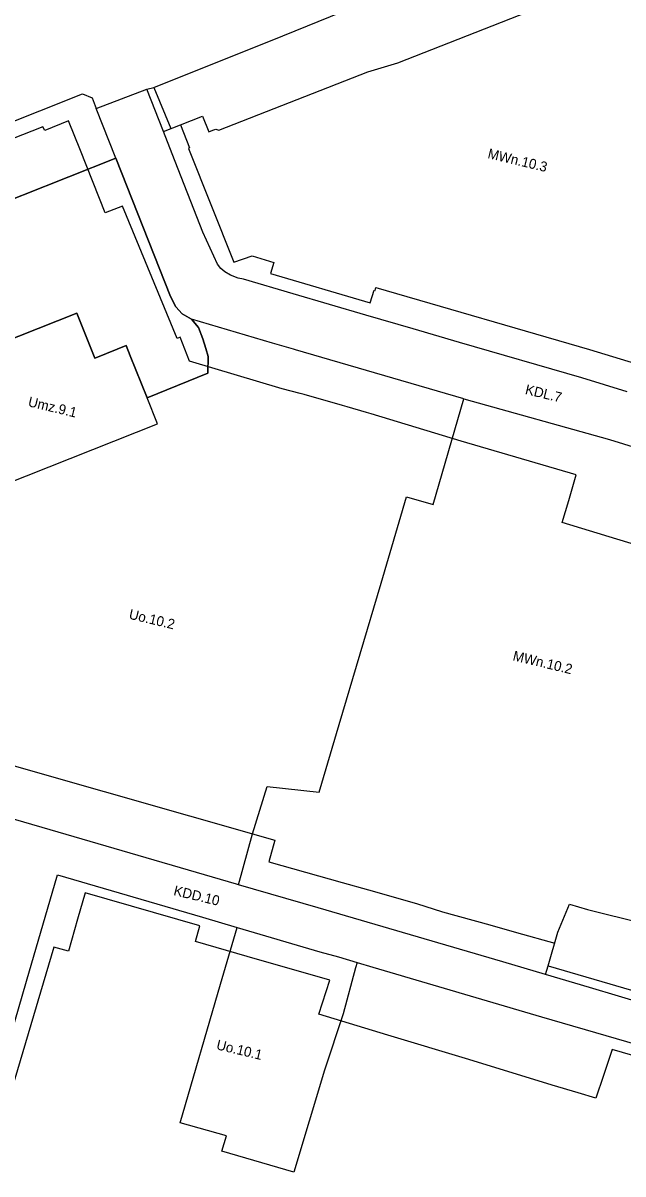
# Model space of a CAD drawing. Extents: x 7429686 to 7432896, y 5547954 to 5550600.
# Drawn here: x 7431748.3 to 7431989.8, y 5548706.1 to 5549169.6 of the extents above; entities that cross this region are included whole.
import ezdxf

# ---------------------------------------------------------------- set-up
doc = ezdxf.new("R2010")
doc.units = 0
for name, color, linetype in [('linie rozgraniczające', 7, 'Continuous'), ('obowiązująca linia zabudowy', 7, 'Continuous'), ('oznaczenia przeznaczeń', 7, 'Continuous')]:
    doc.layers.add(name, color=color, linetype=linetype)

msp = doc.modelspace()

# ---------------------------------------------------------------- linework, layer by layer
at = {"layer": 'linie rozgraniczające'}
for p, q in [((7431785.66, 5549115.2), (7431504.99, 5549003.74)), ((7431818.9, 5549046.91), (7431816.06, 5549050.34)), ((7431820.72, 5549042.45), (7431818.9, 5549046.91))]:
    msp.add_line(p, q, dxfattribs=at)
for points in [[(7431899.21, 5549153.61), (7431965.2, 5549179.6)], [(7431852.81, 5549164.49), (7431877.01, 5549174.22)], [(7431800.96, 5549143.64), (7431852.81, 5549164.49)], [(7431887.04, 5549149.97), (7431899.21, 5549153.61)], [(7431827.07, 5549126.43), (7431887.04, 5549149.97)], [(7431798.07, 5549142.96), (7431800.96, 5549143.64)], [(7431684.85, 5549106.33), (7431772.2, 5549141.08)], [(7431772.2, 5549141.08), (7431776.09, 5549139.4)], [(7431776.09, 5549139.4), (7431777.75, 5549135.22)], [(7431777.75, 5549135.22), (7431798.07, 5549142.96)], [(7431804.77, 5549125.9), (7431798.07, 5549142.96)], [(7431785.66, 5549115.2), (7431777.75, 5549135.22)], [(7431811.66, 5549128.55), (7431820.52, 5549132.11)], [(7431820.52, 5549132.11), (7431823.02, 5549125.78)], [(7431804.77, 5549125.9), (7431811.66, 5549128.55)], [(7431808.3, 5549116.89), (7431804.77, 5549125.9)], [(7431823.02, 5549125.78), (7431824.7, 5549126.43)], [(7431824.7, 5549126.43), (7431825.89, 5549126.82)], [(7431825.89, 5549126.82), (7431827.07, 5549126.43)], [(7431820.72, 5549085.42), (7431808.3, 5549116.89)], [(7431487.65, 5549002.56), (7431490.16, 5549003.53), (7431491.56, 5549004.06), (7431499.75, 5549007.52), (7431502.92, 5549008.85), (7431504.99, 5549003.74), (7431785.66, 5549115.2)], [(7431816.06, 5549050.34), (7431812.4, 5549052.53), (7431809.72, 5549055.33), (7431807.68, 5549059.45), (7431785.66, 5549115.2)], [(7431785.66, 5549115.2), (7431807.68, 5549059.45)], [(7431826.53, 5549072.49), (7431820.72, 5549085.42)], [(7431827.87, 5549070.74), (7431826.53, 5549072.49)], [(7431829.46, 5549069.35), (7431827.87, 5549070.74)], [(7431831.77, 5549067.99), (7431829.46, 5549069.35)], [(7431834.88, 5549066.87), (7431831.77, 5549067.99)], [(7431837.02, 5549066.39), (7431834.88, 5549066.87)], [(7431857.03, 5549060.51), (7431837.02, 5549066.39)], [(7431886.31, 5549051.9), (7431857.03, 5549060.51)], [(7431807.68, 5549059.45), (7431809.72, 5549055.33), (7431812.4, 5549052.53), (7431816.06, 5549050.34)], [(7431798.27, 5549018.65), (7431791.38, 5549035.58), (7431789.74, 5549039.66), (7431778.26, 5549035.05), (7431777.18, 5549034.62), (7431769.87, 5549052.73), (7431730.81, 5549037.32), (7431734.44, 5549028.21), (7431724.7, 5549024.21), (7431741.14, 5548983.95)], [(7431734.44, 5549028.21), (7431730.81, 5549037.32), (7431769.87, 5549052.73), (7431777.18, 5549034.62), (7431778.26, 5549035.05)], [(7431905.33, 5549046.39), (7431886.31, 5549051.9)], [(7431816.06, 5549050.34), (7431818.9, 5549046.91), (7431820.72, 5549042.45), (7431821.8, 5549038.55), (7431822.85, 5549035.29), (7431822.73, 5549028.6), (7431798.27, 5549018.65)], [(7431848.77, 5549040.69), (7431816.06, 5549050.34)], [(7431923.98, 5549040.97), (7431905.33, 5549046.39)], [(7431798.27, 5549018.65), (7431822.73, 5549028.6), (7431822.85, 5549035.29), (7431821.8, 5549038.55), (7431820.72, 5549042.45)], [(7431778.26, 5549035.05), (7431789.74, 5549039.66), (7431791.38, 5549035.58), (7431798.27, 5549018.65)], [(7431857.11, 5549038.25), (7431848.77, 5549040.69)], [(7431857.94, 5549038.01), (7431857.11, 5549038.25)], [(7431925.7, 5549018.22), (7431857.94, 5549038.01)], [(7431973.2, 5549026.64), (7431923.98, 5549040.97)], [(7431991.53, 5549021.11), (7431973.2, 5549026.64)], [(7431802.38, 5549008.24), (7431798.27, 5549018.65)], [(7431913.39, 5548975.67), (7431925.7, 5549018.22)], [(7431925.7, 5549018.22), (7431984.36, 5549001.84)], [(7431741.14, 5548983.95), (7431802.38, 5549008.24)], [(7431984.36, 5549001.84), (7432016.11, 5548992.11)], [(7431892.44, 5548944.03), (7431902.71, 5548978.75)], [(7431902.71, 5548978.75), (7431913.39, 5548975.67)], [(7431875.57, 5548887.09), (7431892.44, 5548944.03)], [(7431867.53, 5548859.9), (7431875.57, 5548887.09)], [(7431840.64, 5548843.13), (7431846.53, 5548862.17)], [(7431846.53, 5548862.17), (7431867.53, 5548859.9)], [(7431834.22, 5548822.81), (7431725.87, 5548854.38)], [(7431834.99, 5548822.59), (7431840.64, 5548843.13)], [(7431749.67, 5548783.7), (7431762.16, 5548826.62)], [(7431762.16, 5548826.62), (7431820.54, 5548809.52)], [(7431834.99, 5548822.59), (7431834.22, 5548822.81)], [(7431867.06, 5548813.22), (7431834.99, 5548822.59)], [(7431963.65, 5548803.42), (7431968.28, 5548814.7)], [(7431968.28, 5548814.7), (7431975.55, 5548812.55)], [(7431941.41, 5548791.48), (7431867.06, 5548813.22)], [(7431975.55, 5548812.55), (7431997.73, 5548807.08)], [(7431820.54, 5548809.52), (7431834.42, 5548805.4)], [(7431827.76, 5548782.57), (7431834.42, 5548805.4)], [(7431834.42, 5548805.4), (7431867.77, 5548795.62)], [(7431959.7, 5548789.91), (7431963.65, 5548803.42)], [(7431867.77, 5548795.62), (7431875.31, 5548793.5)], [(7431875.31, 5548793.5), (7431882.8, 5548791.22)], [(7431958.67, 5548786.41), (7431941.41, 5548791.48)], [(7431882.16, 5548789.08), (7431877.13, 5548770.53)], [(7431882.8, 5548791.22), (7431882.16, 5548789.08)], [(7431882.8, 5548791.22), (7431889.09, 5548789.36)], [(7431889.09, 5548789.36), (7431956.98, 5548769.32)], [(7431958.67, 5548786.41), (7431959.7, 5548789.91)], [(7431731.33, 5548720.67), (7431749.67, 5548783.7)], [(7431811.48, 5548726.7), (7431827.76, 5548782.57)], [(7431976.39, 5548781.2), (7431958.67, 5548786.41)], [(7431999.67, 5548774.22), (7431976.39, 5548781.2)], [(7431877.13, 5548770.53), (7431869.71, 5548747.96)], [(7431956.98, 5548769.32), (7432038.88, 5548745.56)], [(7431869.71, 5548747.96), (7431857.26, 5548706.84)], [(7431830.18, 5548721.4), (7431811.48, 5548726.7)], [(7431828.36, 5548715.23), (7431830.18, 5548721.4)], [(7431857.26, 5548706.84), (7431828.36, 5548715.23)]]:
    msp.add_lwpolyline(points, dxfattribs=at)
at = {"layer": 'obowiązująca linia zabudowy'}
msp.add_line((7431800.96, 5549143.64), (7431807.79, 5549127.06), dxfattribs=at)
for points in [[(7431766.61, 5549130.17), (7431756.99, 5549126.27), (7431756.29, 5549127.83), (7431735.31, 5549119.54)], [(7431815.25, 5549033.35), (7431811.58, 5549043.03), (7431810.34, 5549042.58), (7431788.37, 5549095.82), (7431781.4, 5549093.12), (7431771.39, 5549118.2), (7431766.61, 5549130.17)], [(7431811.66, 5549128.55), (7431815.33, 5549119.34), (7431814.86, 5549119.06), (7431833.18, 5549073.22), (7431840.48, 5549075.78), (7431849.25, 5549073.09), (7431847.84, 5549068.66), (7431888.06, 5549056.88), (7431889.59, 5549061.99), (7431890.02, 5549061.88), (7431890.36, 5549063.02)], [(7431890.36, 5549063.02), (7431976.32, 5549038.08), (7431994.91, 5549032.49), (7432055.44, 5549014.62), (7432056.03, 5549016.4), (7432065.38, 5549013.54), (7432064.81, 5549011.51), (7432078.91, 5549007.17), (7432082.2, 5549019.17), (7432105.85, 5549011.75), (7432117.86, 5549008.18), (7432204.39, 5548982.49), (7432203.42, 5548979.11), (7432202.88, 5548979.27), (7432201.05, 5548972.89), (7432216.61, 5548968.41), (7432221.56, 5548985.6), (7432224.91, 5548984.63), (7432230.18, 5549002.93), (7432227.09, 5549003.82), (7432232.12, 5549021.29), (7432233.49, 5549026.51), (7432234.43, 5549030.05)], [(7431924.63, 5549001.26), (7431888.4, 5549012.24), (7431886.6, 5549012.76), (7431878.76, 5549015.01), (7431876.93, 5549015.56), (7431861.48, 5549019.93), (7431859.81, 5549020.41), (7431852.65, 5549022.34), (7431815.25, 5549033.35)], [(7432073.79, 5548794.14), (7432077.22, 5548807.01), (7432082.7, 5548826), (7432091.23, 5548855.14), (7432084.49, 5548857.14), (7432087.31, 5548866.67), (7432095.91, 5548895.72), (7432088.95, 5548897.74), (7432091.76, 5548907.42), (7432100.2, 5548936.45), (7432091.13, 5548939.15), (7432097.14, 5548960.46), (7432050.78, 5548973.93), (7432048.2, 5548965.02), (7432043.53, 5548948.94), (7432034.3, 5548951.81), (7432033.11, 5548947.97), (7431987.31, 5548961.78), (7431965.36, 5548968.4), (7431967.98, 5548977.35), (7431971, 5548987.66), (7431924.63, 5549001.26)], [(7431577.21, 5548911.2), (7431589.18, 5548907.8), (7431611.32, 5548901.4), (7431623.3, 5548897.83), (7431645.57, 5548891.16), (7431657.48, 5548887.86), (7431679.82, 5548881.19), (7431691.72, 5548877.82), (7431693.9, 5548885.03), (7431746.6, 5548869.97), (7431849.61, 5548840.54), (7431847.29, 5548831.84)], [(7431847.29, 5548831.84), (7431876.82, 5548823.45), (7431887.41, 5548820.48), (7431906.7, 5548814.98), (7431917.22, 5548811.73), (7431936.27, 5548806.45), (7431947, 5548803.38), (7431962.35, 5548798.99)], [(7431773.26, 5548819.35), (7431770.21, 5548808.72), (7431766.52, 5548795.89), (7431760.63, 5548797.5), (7431747.1, 5548751.63), (7431737.24, 5548718.65), (7431724.14, 5548672.46)], [(7432031.3, 5548742.89), (7431985.51, 5548756.24), (7431981.99, 5548745.69), (7431978.94, 5548736.59), (7431971.72, 5548738.72), (7431961.26, 5548741.82), (7431927.75, 5548752.14), (7431895.14, 5548762.01), (7431867.41, 5548770.39), (7431871.83, 5548784.12), (7431838.53, 5548793.74), (7431817.65, 5548799.78), (7431819.43, 5548806.02), (7431773.26, 5548819.35)], [(7431959.7, 5548789.91), (7431993.26, 5548780.1), (7432004.46, 5548776.66), (7432016.7, 5548773.07), (7432020.19, 5548784.68), (7432022.6, 5548784), (7432022.51, 5548783.46), (7432023.25, 5548783.37), (7432029.97, 5548807.17), (7432042.08, 5548803.49), (7432050.04, 5548801.08), (7432049.45, 5548799.14), (7432064.85, 5548794.5), (7432065.64, 5548796.4), (7432073.79, 5548794.14)]]:
    msp.add_lwpolyline(points, dxfattribs=at)

# ---------------------------------------------------------------- texts
at = {"layer": 'oznaczenia przeznaczeń'}
for s, p in [('MWn.10.3', (7431935.09, 5549115.24)), ('KDL.7', (7431950.17, 5549020.24)), ('Umz.9.1', (7431750.03, 5549015.32)), ('Uo.10.2', (7431790.62, 5548929.76)), ('MWn.10.2', (7431945.2, 5548913)), ('KDD.10', (7431808.62, 5548818.45)), ('Uo.10.1', (7431825.85, 5548756.35))]:
    msp.add_text(s, height=4, rotation=346.4891, dxfattribs=at).set_placement(p)

doc.saveas('drawing.dxf')
